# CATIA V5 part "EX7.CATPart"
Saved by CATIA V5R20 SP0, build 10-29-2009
Part number: EX7
Bounding box of the stored display mesh (mm): x -31.004 to 119.256, y -20 to 100, z 0 to 10
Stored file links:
  E:\Nouveau dossier\tarek\mécaniquee\Catia\TP 0\EX7.CATPart
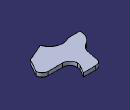
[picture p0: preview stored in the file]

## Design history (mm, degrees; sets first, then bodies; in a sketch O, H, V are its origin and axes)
Set1
  DatumSurface1 to DatumSurface18
Body1 (main body)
